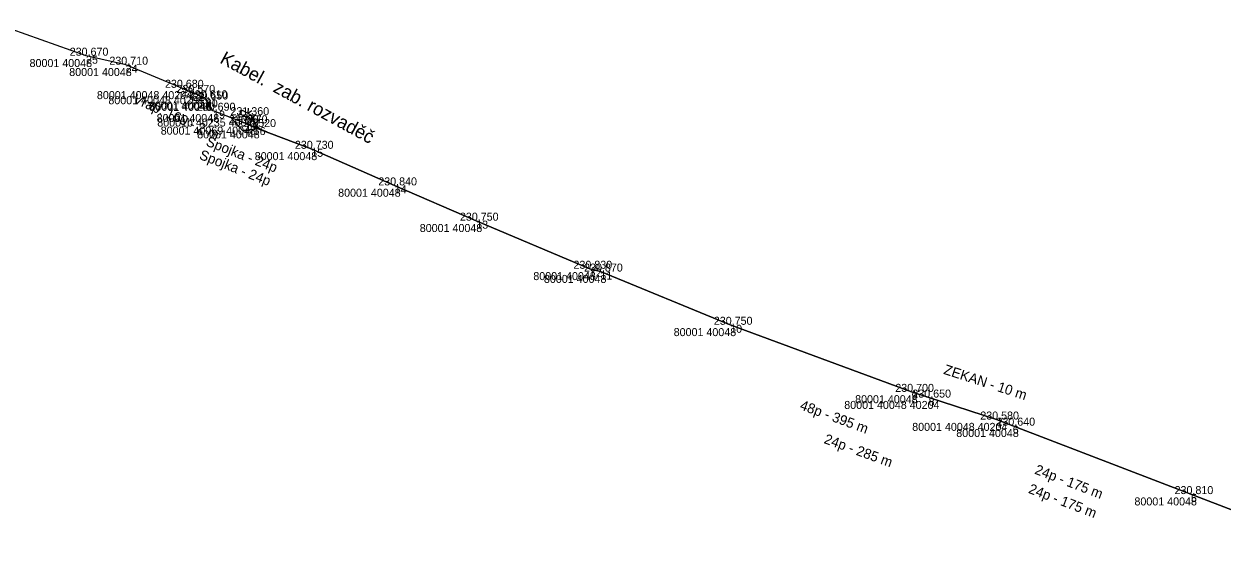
# Model space of a CAD drawing. Extents: x -771675 to -771031, y -1050148 to -1049817.
# Drawn here: x -771414.2 to -771234.6, y -1050072.8 to -1049994.2 of the extents above; entities that cross this region are included whole.
import ezdxf

# ---------------------------------------------------------------- set-up
doc = ezdxf.new("R2010")
doc.units = 0
for name, color, linetype in [('Vrstva 27', 7, 'Continuous'), ('Vrstva 28', 7, 'Continuous'), ('Vrstva 35', 7, 'Continuous'), ('Vrstva 60', 7, 'Continuous'), ('Vrstva 61', 7, 'Continuous'), ('Vrstva 62', 7, 'Continuous')]:
    doc.layers.add(name, color=color, linetype=linetype)

msp = doc.modelspace()

# ---------------------------------------------------------------- linework, layer by layer
at = {"layer": 'Vrstva 27'}
msp.add_line((-771381.55, -1050007.16), (-771381.54, -1050007.15), dxfattribs=at)
msp.add_lwpolyline([(-771381.55, -1050007.15), (-771379.79, -1050008.1), (-771380.11, -1050008.69), (-771381.87, -1050007.74)], close=True, dxfattribs=at)
msp.add_lwpolyline([(-771380.65, -1050006.88), (-771380.67, -1050007.63), (-771380.06, -1050007.2)], dxfattribs=at)
at = {"layer": 'Vrstva 28'}
for p, q in [((-771377.82, -1050010.42), (-771384.32, -1050007.86)), ((-771377.82, -1050010.42), (-771384.32, -1050007.86)), ((-771383.24, -1050008.29), (-771380.64, -1050008.06)), ((-771383.24, -1050008.29), (-771380.64, -1050008.06)), ((-771380.64, -1050008.06), (-771378.9, -1050009.99)), ((-771380.64, -1050008.06), (-771378.9, -1050009.99)), ((-771381.5, -1050010.22), (-771383.24, -1050008.29)), ((-771381.5, -1050010.22), (-771383.24, -1050008.29)), ((-771378.9, -1050009.99), (-771381.5, -1050010.22)), ((-771378.9, -1050009.99), (-771381.5, -1050010.22))]:
    msp.add_line(p, q, dxfattribs=at)
for points in [[(-771381.07, -1050009.14), (-771385.88, -1050007.25), (-771386.97, -1050005.57), (-771387.07, -1050005.38), (-771388.93, -1050004.58), (-771390.65, -1050003.81), (-771398.99, -1050000.35), (-771404.94, -1049999), (-771418.45, -1049994.24)], [(-771381.07, -1050009.14), (-771385.88, -1050007.25), (-771386.97, -1050005.57), (-771387.07, -1050005.38), (-771388.93, -1050004.58), (-771390.65, -1050003.81), (-771398.99, -1050000.35), (-771404.94, -1049999), (-771418.45, -1049994.24)], [(-771380.83, -1050007.92), (-771381.07, -1050009.14), (-771379.8, -1050009.7), (-771371.17, -1050012.96), (-771358.66, -1050018.45), (-771346.42, -1050023.74), (-771329.39, -1050030.95), (-771327.8, -1050031.37), (-771308.34, -1050039.35), (-771281.13, -1050049.41), (-771278.57, -1050050.27), (-771268.38, -1050053.56), (-771265.96, -1050054.48), (-771239.24, -1050064.74), (-771224.8, -1050070.31)], [(-771224.8, -1050070.31), (-771239.24, -1050064.74), (-771265.96, -1050054.48), (-771268.38, -1050053.56), (-771278.57, -1050050.27), (-771281.13, -1050049.41), (-771308.34, -1050039.35), (-771327.8, -1050031.37), (-771329.39, -1050030.95), (-771346.42, -1050023.74), (-771358.66, -1050018.45), (-771371.17, -1050012.96), (-771379.8, -1050009.7), (-771381.07, -1050009.14)], [(-771381.07, -1050009.14), (-771379.8, -1050009.7), (-771371.17, -1050012.96), (-771358.66, -1050018.45), (-771346.42, -1050023.74), (-771329.39, -1050030.95), (-771327.8, -1050031.37), (-771308.34, -1050039.35), (-771281.13, -1050049.41), (-771278.57, -1050050.27), (-771268.38, -1050053.56), (-771265.96, -1050054.48), (-771239.24, -1050064.74), (-771224.8, -1050070.31), (-771218.18, -1050072.83)]]:
    msp.add_lwpolyline(points, dxfattribs=at)
at = {"layer": 'Vrstva 35'}
for p, q in [((-771390.65, -1050003.81), (-771388.93, -1050004.58)), ((-771268.38, -1050053.56), (-771278.57, -1050050.27))]:
    msp.add_line(p, q, dxfattribs=at)
at = {"layer": 'Vrstva 60'}
for p, q in [((-771404.94, -1049999), (-771404.94, -1049999)), ((-771398.99, -1050000.35), (-771398.99, -1050000.35)), ((-771390.65, -1050003.81), (-771390.65, -1050003.81)), ((-771388.93, -1050004.58), (-771388.93, -1050004.58)), ((-771387.07, -1050005.38), (-771387.07, -1050005.38)), ((-771386.97, -1050005.57), (-771386.97, -1050005.57)), ((-771385.88, -1050007.25), (-771385.88, -1050007.25)), ((-771380.83, -1050007.92), (-771380.83, -1050007.92)), ((-771381.07, -1050009.14), (-771381.07, -1050009.14)), ((-771379.8, -1050009.7), (-771379.8, -1050009.7)), ((-771371.17, -1050012.96), (-771371.17, -1050012.96)), ((-771358.66, -1050018.45), (-771358.66, -1050018.45)), ((-771346.42, -1050023.74), (-771346.42, -1050023.74)), ((-771329.39, -1050030.95), (-771329.39, -1050030.95)), ((-771327.8, -1050031.37), (-771327.8, -1050031.37)), ((-771308.34, -1050039.35), (-771308.34, -1050039.35)), ((-771281.13, -1050049.41), (-771281.13, -1050049.41)), ((-771278.57, -1050050.27), (-771278.57, -1050050.27)), ((-771268.38, -1050053.56), (-771268.38, -1050053.56)), ((-771265.96, -1050054.48), (-771265.96, -1050054.48)), ((-771239.24, -1050064.74), (-771239.24, -1050064.74))]:
    msp.add_line(p, q, dxfattribs=at)

# ---------------------------------------------------------------- texts
at = {"layer": 'Vrstva 27'}
msp.add_text('Kabel.  zab. rozvaděč', height=2, rotation=331.4945, dxfattribs=at).set_placement((-771385, -1050000))
at = {"layer": 'Vrstva 28'}
for s, rotation, p in [('Spojka - 24p', 338.5486, (-771387.08, -1050012.44)), ('Spojka - 24p', 338.5486, (-771388.08, -1050014.44)), ('48p - 395 m', 339.7098, (-771298, -1050052)), ('24p - 285 m', 339.9462, (-771294.38, -1050057.07)), ('24p - 175 m', 338.9941, (-771262.79, -1050061.65)), ('24p - 175 m', 338.9941, (-771263.72, -1050064.53))]:
    msp.add_text(s, height=1.5, rotation=rotation, dxfattribs=at).set_placement(p)
at = {"layer": 'Vrstva 35'}
for s, rotation, p in [('Vrap. 160 - 2 m', 335.8832, (-771398, -1050006)), ('ZEKAN - 10 m', 342.1065, (-771276.44, -1050046.69))]:
    msp.add_text(s, height=1.5, rotation=rotation, dxfattribs=at).set_placement(p)
at = {"layer": 'Vrstva 60'}
for s, p in [('25', (-771404.94, -1050000.2)), ('24', (-771398.99, -1050001.55)), ('23', (-771390.65, -1050005.01)), ('22', (-771388.93, -1050005.78)), ('21', (-771387.07, -1050006.58)), ('20', (-771386.97, -1050006.77)), ('19', (-771385.88, -1050008.45)), ('89', (-771380.83, -1050009.12)), ('17', (-771381.07, -1050010.34)), ('16', (-771379.8, -1050010.9)), ('15', (-771371.17, -1050014.16)), ('14', (-771358.66, -1050019.65)), ('13', (-771346.42, -1050024.94)), ('12', (-771329.39, -1050032.15)), ('11', (-771327.8, -1050032.57)), ('10', (-771308.34, -1050040.55)), ('9', (-771281.13, -1050050.61)), ('8', (-771278.57, -1050051.47)), ('7', (-771268.38, -1050054.76)), ('6', (-771265.96, -1050055.68)), ('5', (-771239.24, -1050065.94))]:
    msp.add_text(s, height=1.2, dxfattribs=at).set_placement(p)
at = {"layer": 'Vrstva 61'}
for s, p in [('230.670', (-771407.39, -1049999)), ('230.710', (-771401.44, -1050000.35)), ('230.680', (-771393.1, -1050003.81)), ('230.570', (-771391.38, -1050004.58)), ('230.610', (-771389.52, -1050005.38)), ('230.650', (-771389.42, -1050005.57)), ('230.690', (-771388.33, -1050007.25)), ('230.470', (-771383.52, -1050009.14)), ('231.360', (-771383.28, -1050007.92)), ('230.520', (-771382.25, -1050009.7)), ('230.730', (-771373.62, -1050012.96)), ('230.840', (-771361.11, -1050018.45)), ('230.750', (-771348.87, -1050023.74)), ('230.830', (-771331.84, -1050030.95)), ('230.870', (-771330.25, -1050031.37)), ('230.750', (-771310.79, -1050039.35)), ('230.700', (-771283.58, -1050049.41)), ('230.650', (-771281.02, -1050050.27)), ('230.580', (-771270.83, -1050053.56)), ('230.640', (-771268.41, -1050054.48)), ('230.810', (-771241.69, -1050064.74))]:
    msp.add_text(s, height=1.2, dxfattribs=at).set_placement(p)
at = {"layer": 'Vrstva 62'}
for s, p in [('80001 40048', (-771413.41, -1050000.7)), ('80001 40048', (-771407.46, -1050002.05)), ('80001 40048 40204', (-771403.31, -1050005.51)), ('80001 40048 40204', (-771401.59, -1050006.28)), ('80001 40048', (-771395.54, -1050007.08)), ('80001 40048', (-771395.44, -1050007.27)), ('80001 40048', (-771394.35, -1050008.95)), ('80001b 40235 40048', (-771394.26, -1050009.62)), ('80001 40069 40048', (-771393.74, -1050010.84)), ('80001 40048', (-771388.27, -1050011.4)), ('80001 40048', (-771379.64, -1050014.66)), ('80001 40048', (-771367.13, -1050020.15)), ('80001 40048', (-771354.89, -1050025.44)), ('80001 40048', (-771337.86, -1050032.65)), ('80001 40048', (-771336.27, -1050033.07)), ('80001 40048', (-771316.81, -1050041.05)), ('80001 40048 40204', (-771291.23, -1050051.97)), ('80001 40048', (-771289.6, -1050051.11)), ('80001 40048 40204', (-771281.04, -1050055.26)), ('80001 40048', (-771274.43, -1050056.18)), ('80001 40048', (-771247.71, -1050066.44))]:
    msp.add_text(s, height=1.2, dxfattribs=at).set_placement(p)

doc.saveas('drawing.dxf')
